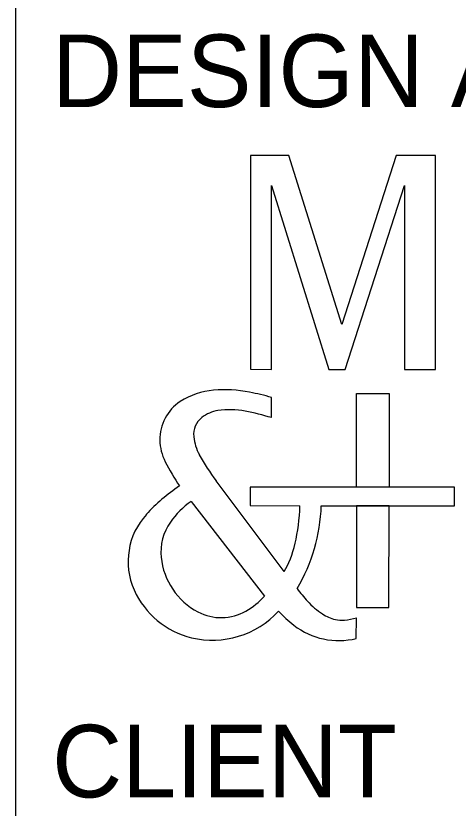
# Model space of a CAD drawing. Extents: x -3.9 to 34, y 0 to 22.
# Drawn here: x 32 to 32.61, y 3.384 to 4.476 of the extents above; entities that cross this region are included whole.
import ezdxf

# ---------------------------------------------------------------- set-up
doc = ezdxf.new("R2010")
doc.units = 0
for name, color, linetype in [('PM_P_Crosswalk', 7, 'Continuous'), ('PM_P_Edge_Line', 7, 'Continuous'), ('SN_P_Signs', 7, 'Continuous')]:
    doc.layers.add(name, color=color, linetype=linetype)

msp = doc.modelspace()

# ---------------------------------------------------------------- linework, layer by layer
at = {"layer": 'PM_P_Crosswalk'}
for p, q in [((32.4696, 3.8261), (32.4697, 3.9552)), ((32.4697, 3.9552), (32.5147, 3.9552)), ((32.5147, 3.9552), (32.5146, 3.8261)), ((32.3525, 3.922), (32.3525, 3.9497)), ((32.37, 3.7101), (32.2762, 3.8349)), ((32.2416, 3.8065), (32.3429, 3.6759)), ((32.4696, 3.8006), (32.4696, 3.6605)), ((32.5146, 3.8006), (32.4696, 3.8006)), ((32.5145, 3.6605), (32.5146, 3.8006)), ((32.1797, 3.7884), (32.18, 3.7887)), ((32.4696, 3.6605), (32.5145, 3.6605)), ((32.4694, 3.6176), (32.4695, 3.646))]:
    msp.add_line(p, q, dxfattribs=at)
msp.add_lwpolyline([(32.3526, 3.9885), (32.3527, 4.2417), (32.4317, 3.9885), (32.4542, 3.9885), (32.536, 4.2417), (32.5359, 3.9885), (32.5784, 3.9885), (32.5785, 4.2831), (32.5246, 4.2831), (32.4495, 4.0504), (32.3765, 4.2832), (32.3235, 4.2832), (32.3234, 3.9886)], close=True, dxfattribs=at)
msp.add_lwpolyline([(32.3526, 3.9885), (32.3527, 4.2417), (32.4317, 3.9885), (32.4542, 3.9885), (32.536, 4.2417), (32.5359, 3.9885), (32.5784, 3.9885), (32.5785, 4.2831), (32.5246, 4.2831), (32.4495, 4.0504), (32.3765, 4.2832), (32.3235, 4.2832), (32.3234, 3.9886)], close=True, dxfattribs=at)
msp.add_lwpolyline([(32.4211, 3.8006), (32.6049, 3.8006), (32.6049, 3.8261), (32.3233, 3.8261), (32.3233, 3.8007), (32.3916, 3.8006)], dxfattribs=at)
for centre, radius, start, end in [((32.2803, 3.862), 0.0981, 94.5206, 123.1061), ((32.2871, 3.7753), 0.1851, 79.0563, 94.5206), ((32.2546, 3.6069), 0.3566, 74.0516, 79.0563), ((32.2606, 3.8922), 0.062, 123.1061, 181.2152), ((32.2855, 3.8851), 0.0471, 98.3723, 128.329), ((32.2951, 3.8196), 0.1132, 79.2666, 98.3723), ((32.2746, 3.8989), 0.0295, 128.329, 186.0821), ((32.2495, 3.579), 0.3581, 73.2803, 79.2666), ((32.2669, 3.8924), 0.0684, 181.2152, 207.1091), ((32.3115, 3.9028), 0.0666, 186.0821, 208.5769), ((32.5116, 4.0118), 0.2945, 208.5769, 216.933), ((32.517, 4.0204), 0.3493, 207.1091, 213.4656), ((32.3628, 3.6213), 0.2479, 123.6, 137.6035), ((32.3108, 3.7092), 0.1194, 125.3927, 144.9042), ((32.1831, 3.8084), 0.2382, 329.2356, 358.1314), ((32.2512, 3.7236), 0.0964, 137.6035, 203.9313), ((32.2717, 3.7366), 0.0717, 144.9042, 185.7554), ((32.2959, 3.7391), 0.096, 185.7554, 242.1528), ((32.2691, 3.7316), 0.116, 203.9313, 256.6813), ((32.5828, 3.8332), 0.2441, 216.933, 222.2898), ((32.2633, 3.7491), 0.1081, 299.979, 317.3992), ((32.4823, 3.7418), 0.1082, 222.2898, 236.5762), ((32.271, 3.7399), 0.1246, 256.6813, 317.1089), ((32.2831, 3.7148), 0.0685, 242.1528, 299.979), ((32.487, 3.7702), 0.1697, 222.685, 232.3525), ((32.453, 3.6975), 0.0551, 236.5762, 256.9728), ((32.4497, 3.6832), 0.0405, 256.9728, 275.0638), ((32.446, 3.7257), 0.0831, 275.0638, 286.4619), ((32.4453, 3.7161), 0.1014, 232.3525, 283.7629)]:
    msp.add_arc(centre, radius, start, end, dxfattribs=at)
msp.add_ellipse((32.351, 3.8018), major_axis=(-0.0031, -0.1077), ratio=0.377453, start_param=0.562501, end_param=1.570796, dxfattribs=at)
at = {"layer": 'PM_P_Edge_Line'}
msp.add_line((32, 0.5), (32, 21.5), dxfattribs=at)

# ---------------------------------------------------------------- texts
at = {"layer": 'PM_P_Crosswalk'}
msp.add_text('DESIGN AGENCY', height=0.1, dxfattribs=at).set_placement((32.05, 4.35))
at = {"layer": 'SN_P_Signs'}
msp.add_text('CLIENT', height=0.1, dxfattribs=at).set_placement((32.05, 3.3986))

doc.saveas('drawing.dxf')
